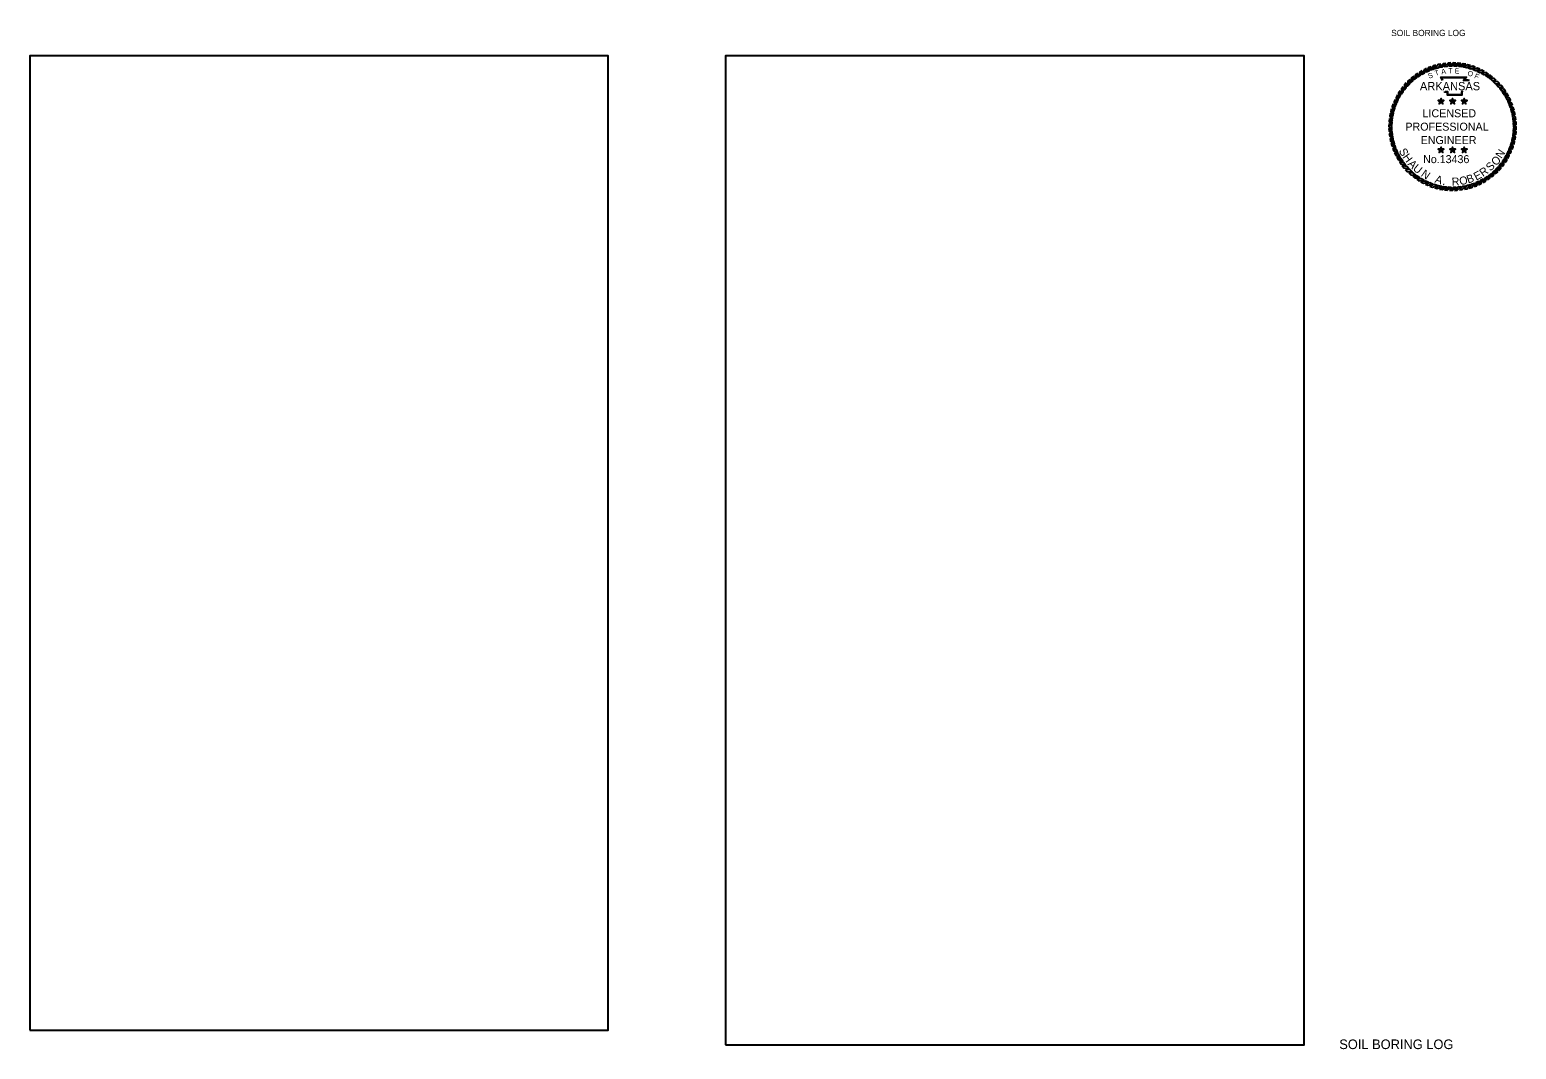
# Model space of a CAD drawing. Extents: x 1186737.8 to 1186765.7, y 251518.3 to 251537.4.
import ezdxf

# ---------------------------------------------------------------- set-up
doc = ezdxf.new("R2010")
doc.units = 0
for name, color, linetype in [('1', 7, 'Continuous'), ('60', 7, 'Continuous'), ('G-ANNO-SYMB', 7, 'Continuous')]:
    doc.layers.add(name, color=color, linetype=linetype)

msp = doc.modelspace()

# ---------------------------------------------------------------- linework, layer by layer
at = {"layer": '1'}
for points in [[(1186737.826, 251518.614), (1186748.672, 251518.614), (1186748.672, 251536.869), (1186737.826, 251536.869)], [(1186750.871, 251518.341), (1186761.718, 251518.341), (1186761.718, 251536.869), (1186750.871, 251536.869)]]:
    msp.add_lwpolyline(points, close=True, dxfattribs=at)
at = {"layer": 'G-ANNO-SYMB'}
for points in [[(1186763.928, 251536.59), (1186763.883, 251536.565), (1186763.851, 251536.479), (1186763.898, 251536.509)], [(1186764.012, 251536.632), (1186763.966, 251536.61), (1186763.927, 251536.527), (1186763.975, 251536.554)], [(1186764.099, 251536.667), (1186764.051, 251536.649), (1186764.006, 251536.569), (1186764.056, 251536.592)], [(1186764.188, 251536.695), (1186764.139, 251536.68), (1186764.088, 251536.605), (1186764.14, 251536.623)], [(1186764.28, 251536.716), (1186764.229, 251536.705), (1186764.172, 251536.634), (1186764.226, 251536.648)], [(1186764.372, 251536.729), (1186764.321, 251536.723), (1186764.259, 251536.656), (1186764.313, 251536.666)], [(1186764.466, 251536.736), (1186764.414, 251536.733), (1186764.347, 251536.671), (1186764.402, 251536.677)], [(1186764.559, 251536.735), (1186764.508, 251536.736), (1186764.436, 251536.68), (1186764.491, 251536.682)], [(1186764.653, 251536.726), (1186764.602, 251536.732), (1186764.525, 251536.681), (1186764.581, 251536.679)], [(1186764.745, 251536.711), (1186764.695, 251536.72), (1186764.615, 251536.676), (1186764.67, 251536.669)], [(1186764.836, 251536.688), (1186764.786, 251536.701), (1186764.703, 251536.663), (1186764.757, 251536.652)], [(1186764.925, 251536.658), (1186764.876, 251536.675), (1186764.79, 251536.644), (1186764.844, 251536.628)], [(1186765.011, 251536.621), (1186764.964, 251536.642), (1186764.876, 251536.618), (1186764.928, 251536.598)], [(1186765.094, 251536.578), (1186765.049, 251536.602), (1186764.959, 251536.585), (1186765.009, 251536.561)], [(1186763.571, 251536.292), (1186763.539, 251536.251), (1186763.543, 251536.16), (1186763.574, 251536.205)], [(1186763.632, 251536.362), (1186763.598, 251536.324), (1186763.594, 251536.233), (1186763.629, 251536.276)], [(1186763.699, 251536.428), (1186763.662, 251536.393), (1186763.651, 251536.302), (1186763.689, 251536.342)], [(1186763.771, 251536.488), (1186763.731, 251536.456), (1186763.713, 251536.366), (1186763.754, 251536.403)], [(1186763.848, 251536.542), (1186763.805, 251536.513), (1186763.78, 251536.425), (1186763.824, 251536.459)], [(1186765.173, 251536.528), (1186765.13, 251536.556), (1186765.039, 251536.546), (1186765.088, 251536.518)], [(1186765.248, 251536.472), (1186765.208, 251536.503), (1186765.116, 251536.5), (1186765.162, 251536.469)], [(1186765.319, 251536.41), (1186765.281, 251536.445), (1186765.19, 251536.449), (1186765.233, 251536.414)], [(1186765.385, 251536.344), (1186765.349, 251536.381), (1186765.259, 251536.392), (1186765.299, 251536.354)], [(1186765.445, 251536.272), (1186765.412, 251536.312), (1186765.323, 251536.33), (1186765.36, 251536.289)], [(1186763.422, 251536.054), (1186763.401, 251536.007), (1186763.425, 251535.919), (1186763.445, 251535.971)], [(1186763.465, 251536.137), (1186763.44, 251536.092), (1186763.458, 251536.002), (1186763.481, 251536.052)], [(1186763.515, 251536.216), (1186763.487, 251536.173), (1186763.497, 251536.083), (1186763.525, 251536.131)], [(1186764.282, 251536.018), (1186764.269, 251536.035), (1186764.23, 251536.035), (1186764.262, 251536.012)], [(1186764.282, 251536.018), (1186764.262, 251536.012), (1186764.25, 251535.974), (1186764.282, 251535.997)], [(1186764.282, 251536.018), (1186764.294, 251536.035), (1186764.282, 251536.073), (1186764.269, 251536.035)], [(1186764.282, 251536.018), (1186764.301, 251536.012), (1186764.333, 251536.035), (1186764.294, 251536.035)], [(1186764.282, 251536.018), (1186764.282, 251535.997), (1186764.314, 251535.974), (1186764.301, 251536.012)], [(1186764.5, 251536.018), (1186764.488, 251536.035), (1186764.448, 251536.035), (1186764.48, 251536.012)], [(1186764.5, 251536.018), (1186764.48, 251536.012), (1186764.468, 251535.974), (1186764.5, 251535.997)], [(1186764.5, 251536.018), (1186764.512, 251536.035), (1186764.5, 251536.073), (1186764.488, 251536.035)], [(1186764.5, 251536.018), (1186764.52, 251536.012), (1186764.552, 251536.035), (1186764.512, 251536.035)], [(1186764.5, 251536.018), (1186764.5, 251535.997), (1186764.532, 251535.974), (1186764.52, 251536.012)], [(1186764.718, 251536.018), (1186764.706, 251536.035), (1186764.666, 251536.035), (1186764.698, 251536.012)], [(1186764.718, 251536.018), (1186764.698, 251536.012), (1186764.686, 251535.974), (1186764.718, 251535.997)], [(1186764.718, 251536.018), (1186764.73, 251536.035), (1186764.718, 251536.073), (1186764.706, 251536.035)], [(1186764.718, 251536.018), (1186764.738, 251536.012), (1186764.77, 251536.035), (1186764.73, 251536.035)], [(1186764.718, 251536.018), (1186764.718, 251535.997), (1186764.75, 251535.974), (1186764.738, 251536.012)], [(1186765.499, 251536.195), (1186765.47, 251536.238), (1186765.382, 251536.263), (1186765.416, 251536.219)], [(1186765.547, 251536.115), (1186765.521, 251536.159), (1186765.436, 251536.191), (1186765.466, 251536.145)], [(1186765.589, 251536.031), (1186765.567, 251536.077), (1186765.484, 251536.116), (1186765.511, 251536.067)], [(1186765.624, 251535.944), (1186765.605, 251535.992), (1186765.526, 251536.037), (1186765.549, 251535.986)], [(1186763.332, 251535.788), (1186763.323, 251535.738), (1186763.367, 251535.658), (1186763.374, 251535.713)], [(1186763.355, 251535.879), (1186763.342, 251535.83), (1186763.379, 251535.746), (1186763.391, 251535.801)], [(1186763.385, 251535.968), (1186763.368, 251535.92), (1186763.399, 251535.834), (1186763.414, 251535.887)], [(1186765.652, 251535.855), (1186765.637, 251535.904), (1186765.561, 251535.955), (1186765.58, 251535.903)], [(1186765.672, 251535.763), (1186765.662, 251535.813), (1186765.59, 251535.87), (1186765.605, 251535.817)], [(1186765.686, 251535.671), (1186765.68, 251535.721), (1186765.613, 251535.784), (1186765.623, 251535.729)], [(1186763.308, 251535.603), (1186763.307, 251535.551), (1186763.363, 251535.479), (1186763.361, 251535.535)], [(1186763.307, 251535.509), (1186763.31, 251535.458), (1186763.371, 251535.39), (1186763.365, 251535.445)], [(1186763.316, 251535.696), (1186763.311, 251535.645), (1186763.361, 251535.569), (1186763.364, 251535.624)], [(1186765.693, 251535.577), (1186765.69, 251535.628), (1186765.628, 251535.696), (1186765.634, 251535.641)], [(1186765.683, 251535.39), (1186765.689, 251535.441), (1186765.638, 251535.517), (1186765.636, 251535.462)], [(1186765.692, 251535.483), (1186765.693, 251535.535), (1186765.637, 251535.607), (1186765.638, 251535.551)], [(1186763.313, 251535.415), (1186763.32, 251535.365), (1186763.387, 251535.302), (1186763.377, 251535.357)], [(1186763.327, 251535.323), (1186763.338, 251535.273), (1186763.409, 251535.216), (1186763.395, 251535.269)], [(1186763.348, 251535.231), (1186763.362, 251535.182), (1186763.438, 251535.131), (1186763.42, 251535.183)], [(1186765.578, 251535.032), (1186765.599, 251535.079), (1186765.575, 251535.167), (1186765.555, 251535.115)], [(1186765.615, 251535.118), (1186765.632, 251535.166), (1186765.601, 251535.252), (1186765.585, 251535.199)], [(1186765.645, 251535.207), (1186765.658, 251535.256), (1186765.62, 251535.34), (1186765.609, 251535.285)], [(1186765.668, 251535.298), (1186765.677, 251535.348), (1186765.633, 251535.428), (1186765.626, 251535.373)], [(1186763.376, 251535.142), (1186763.394, 251535.094), (1186763.474, 251535.049), (1186763.451, 251535.1)], [(1186763.411, 251535.055), (1186763.433, 251535.009), (1186763.516, 251534.97), (1186763.489, 251535.019)], [(1186763.453, 251534.971), (1186763.478, 251534.927), (1186763.564, 251534.895), (1186763.533, 251534.941)], [(1186763.501, 251534.891), (1186763.53, 251534.848), (1186763.618, 251534.823), (1186763.584, 251534.867)], [(1186764.282, 251535.104), (1186764.269, 251535.121), (1186764.23, 251535.121), (1186764.262, 251535.098)], [(1186764.282, 251535.104), (1186764.262, 251535.098), (1186764.25, 251535.06), (1186764.282, 251535.084)], [(1186764.282, 251535.104), (1186764.294, 251535.121), (1186764.282, 251535.159), (1186764.269, 251535.121)], [(1186764.282, 251535.104), (1186764.301, 251535.098), (1186764.333, 251535.121), (1186764.294, 251535.121)], [(1186764.282, 251535.104), (1186764.282, 251535.084), (1186764.314, 251535.06), (1186764.301, 251535.098)], [(1186764.5, 251535.104), (1186764.488, 251535.121), (1186764.448, 251535.121), (1186764.48, 251535.098)], [(1186764.5, 251535.104), (1186764.48, 251535.098), (1186764.468, 251535.06), (1186764.5, 251535.084)], [(1186764.5, 251535.104), (1186764.512, 251535.121), (1186764.5, 251535.159), (1186764.488, 251535.121)], [(1186764.5, 251535.104), (1186764.52, 251535.098), (1186764.552, 251535.121), (1186764.512, 251535.121)], [(1186764.5, 251535.104), (1186764.5, 251535.084), (1186764.532, 251535.06), (1186764.52, 251535.098)], [(1186764.718, 251535.104), (1186764.706, 251535.121), (1186764.666, 251535.121), (1186764.698, 251535.098)], [(1186764.718, 251535.104), (1186764.698, 251535.098), (1186764.686, 251535.06), (1186764.718, 251535.084)], [(1186764.718, 251535.104), (1186764.73, 251535.121), (1186764.718, 251535.159), (1186764.706, 251535.121)], [(1186764.718, 251535.104), (1186764.738, 251535.098), (1186764.77, 251535.121), (1186764.73, 251535.121)], [(1186764.718, 251535.104), (1186764.718, 251535.084), (1186764.75, 251535.06), (1186764.738, 251535.098)], [(1186765.429, 251534.794), (1186765.46, 251534.835), (1186765.457, 251534.926), (1186765.426, 251534.881)], [(1186765.485, 251534.87), (1186765.513, 251534.913), (1186765.502, 251535.003), (1186765.475, 251534.955)], [(1186765.535, 251534.949), (1186765.559, 251534.994), (1186765.542, 251535.084), (1186765.518, 251535.034)], [(1186763.555, 251534.814), (1186763.587, 251534.774), (1186763.677, 251534.756), (1186763.639, 251534.797)], [(1186763.615, 251534.742), (1186763.65, 251534.705), (1186763.741, 251534.694), (1186763.701, 251534.732)], [(1186763.681, 251534.676), (1186763.719, 251534.641), (1186763.81, 251534.637), (1186763.767, 251534.672)], [(1186763.751, 251534.614), (1186763.792, 251534.583), (1186763.883, 251534.586), (1186763.837, 251534.617)], [(1186765.152, 251534.544), (1186765.194, 251534.573), (1186765.22, 251534.661), (1186765.176, 251534.627)], [(1186765.228, 251534.598), (1186765.268, 251534.63), (1186765.287, 251534.72), (1186765.246, 251534.683)], [(1186765.3, 251534.658), (1186765.338, 251534.693), (1186765.349, 251534.784), (1186765.311, 251534.744)], [(1186765.367, 251534.724), (1186765.402, 251534.762), (1186765.406, 251534.853), (1186765.371, 251534.81)], [(1186763.826, 251534.558), (1186763.869, 251534.53), (1186763.96, 251534.54), (1186763.912, 251534.568)], [(1186763.906, 251534.508), (1186763.951, 251534.484), (1186764.041, 251534.501), (1186763.99, 251534.525)], [(1186763.989, 251534.465), (1186764.036, 251534.444), (1186764.124, 251534.468), (1186764.072, 251534.488)], [(1186764.075, 251534.428), (1186764.123, 251534.411), (1186764.209, 251534.442), (1186764.156, 251534.458)], [(1186764.164, 251534.398), (1186764.213, 251534.385), (1186764.296, 251534.423), (1186764.242, 251534.434)], [(1186764.255, 251534.375), (1186764.305, 251534.366), (1186764.385, 251534.41), (1186764.33, 251534.417)], [(1186764.347, 251534.36), (1186764.398, 251534.354), (1186764.474, 251534.405), (1186764.419, 251534.407)], [(1186764.44, 251534.351), (1186764.492, 251534.35), (1186764.564, 251534.406), (1186764.508, 251534.404)], [(1186764.534, 251534.35), (1186764.585, 251534.353), (1186764.653, 251534.415), (1186764.597, 251534.409)], [(1186764.627, 251534.357), (1186764.678, 251534.363), (1186764.741, 251534.43), (1186764.686, 251534.42)], [(1186764.72, 251534.37), (1186764.77, 251534.381), (1186764.827, 251534.452), (1186764.774, 251534.438)], [(1186764.811, 251534.391), (1186764.861, 251534.406), (1186764.912, 251534.481), (1186764.86, 251534.463)], [(1186764.901, 251534.419), (1186764.949, 251534.437), (1186764.994, 251534.517), (1186764.943, 251534.494)], [(1186764.988, 251534.454), (1186765.034, 251534.476), (1186765.073, 251534.559), (1186765.024, 251534.532)], [(1186765.072, 251534.496), (1186765.116, 251534.521), (1186765.148, 251534.607), (1186765.102, 251534.577)]]:
    msp.add_lwpolyline(points, close=True, dxfattribs=at)
for points in [[(1186764.309, 251536.409), (1186764.281, 251536.469), (1186764.762, 251536.47), (1186764.722, 251536.419), (1186764.755, 251536.419), (1186764.782, 251536.42), (1186764.809, 251536.417)], [(1186764.316, 251536.412), (1186764.293, 251536.462), (1186764.746, 251536.462), (1186764.706, 251536.411), (1186764.755, 251536.412), (1186764.782, 251536.412), (1186764.808, 251536.409)], [(1186764.686, 251536.207), (1186764.678, 251536.201), (1186764.675, 251536.191), (1186764.673, 251536.166), (1186764.673, 251536.132), (1186764.404, 251536.132), (1186764.404, 251536.177), (1186764.404, 251536.187), (1186764.393, 251536.191), (1186764.355, 251536.191), (1186764.348, 251536.201)], [(1186764.681, 251536.213), (1186764.671, 251536.205), (1186764.668, 251536.192), (1186764.665, 251536.166), (1186764.665, 251536.14), (1186764.412, 251536.14), (1186764.412, 251536.177), (1186764.412, 251536.193), (1186764.394, 251536.198), (1186764.359, 251536.198), (1186764.354, 251536.205)]]:
    msp.add_lwpolyline(points, dxfattribs=at)

# ---------------------------------------------------------------- texts
at = {"layer": '1'}
msp.add_text('SOIL BORING LOG', height=0.11724, dxfattribs=at).set_placement((1186763.348, 251537.24))
at = {"layer": '60'}
msp.add_text('SOIL BORING LOG', height=0.18, dxfattribs=at).set_placement((1186762.375, 251518.261))
at = {"layer": 'G-ANNO-SYMB'}
for s, height, rotation, p in [('T', 0.0949, 16.9015, (1186764.179, 251536.495)), ('A', 0.0949, 8.6788, (1186764.294, 251536.525)), ('T', 0.0949, 1.4789, (1186764.417, 251536.544)), ('E', 0.0949, 356.672, (1186764.538, 251536.541)), ('O', 0.0949, 341.2218, (1186764.769, 251536.508)), ('ARKANSAS', 0.1549, 360, (1186763.887, 251536.225)), ('S', 0.0949, 19.7726, (1186764.058, 251536.441)), ('F', 0.0949, 335.3628, (1186764.897, 251536.458)), ('LICENSED', 0.15, 360, (1186763.936, 251535.719)), ('PROFESSIONAL', 0.15, 360, (1186763.614, 251535.468)), ('ENGINEER', 0.15, 360, (1186763.9, 251535.217)), ('S', 0.15, 298.1636, (1186763.486, 251535.091)), ('H', 0.15, 305.619, (1186763.555, 251534.973)), ('A', 0.15, 313.4472, (1186763.65, 251534.837)), ('No.13436', 0.1494, 360, (1186763.947, 251534.86)), ('O', 0.15, 44.7757, (1186765.31, 251534.799)), ('N', 0.15, 56.1007, (1186765.415, 251534.934)), ('U', 0.15, 320.9026, (1186763.743, 251534.739)), ('N', 0.15, 324.9326, (1186763.895, 251534.627)), ('A', 0.15, 343.0991, (1186764.156, 251534.498)), ('O', 0.15, 11.4296, (1186764.641, 251534.445)), ('B', 0.15, 18.885, (1186764.791, 251534.477)), ('E', 0.15, 27.8315, (1186764.943, 251534.531)), ('R', 0.15, 35.6597, (1186765.069, 251534.598)), ('S', 0.15, 43.4878, (1186765.207, 251534.7)), ('.', 0.15, 351.3, (1186764.303, 251534.455)), ('R', 0.15, 3.2287, (1186764.487, 251534.436))]:
    msp.add_text(s, height=height, rotation=rotation, dxfattribs=at).set_placement(p)

doc.saveas('drawing.dxf')
